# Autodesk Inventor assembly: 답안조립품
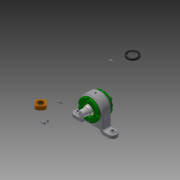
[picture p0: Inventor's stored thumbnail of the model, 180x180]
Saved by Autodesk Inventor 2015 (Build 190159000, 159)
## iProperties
Created: 2019-05
Part Number: 답안조립품
Document SubType Name: Assembly
Designer: 10403
Author: 10403
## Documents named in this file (13)
- C:\Users\10403\Desktop\490504V1038\답안조립품.iam
- C:\Users\10403\Desktop\490504V1038\개스킷.ipt
- C:\Users\10403\Desktop\490504V1038\그리스니플 M6.ipt
- 그리스니플  M6.ipt
- C:\Users\10403\Desktop\490504V1038\그리스니플개스킷.ipt
- C:\Users\10403\Desktop\490504V1038\베어링너트.ipt
- C:\Users\10403\Desktop\490504V1038\본체.ipt
- C:\Users\10403\Desktop\490504V1038\볼트 M4.ipt
- C:\Users\10403\Desktop\490504V1038\앵귤러 볼 베어링 7205.ipt
- C:\Users\10403\Desktop\490504V1038\오일 실 28 40 5 B.ipt
- C:\Users\10403\Desktop\490504V1038\축.ipt
- C:\Users\10403\Desktop\490504V1038\칼라.ipt
- C:\Users\10403\Desktop\490504V1038\커버.ipt
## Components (4 placed, 3 different names)
1. 개스킷:1
2. 그리스니플  M6:1
3. 그리스니플개스킷:1
4. 개스킷:2
